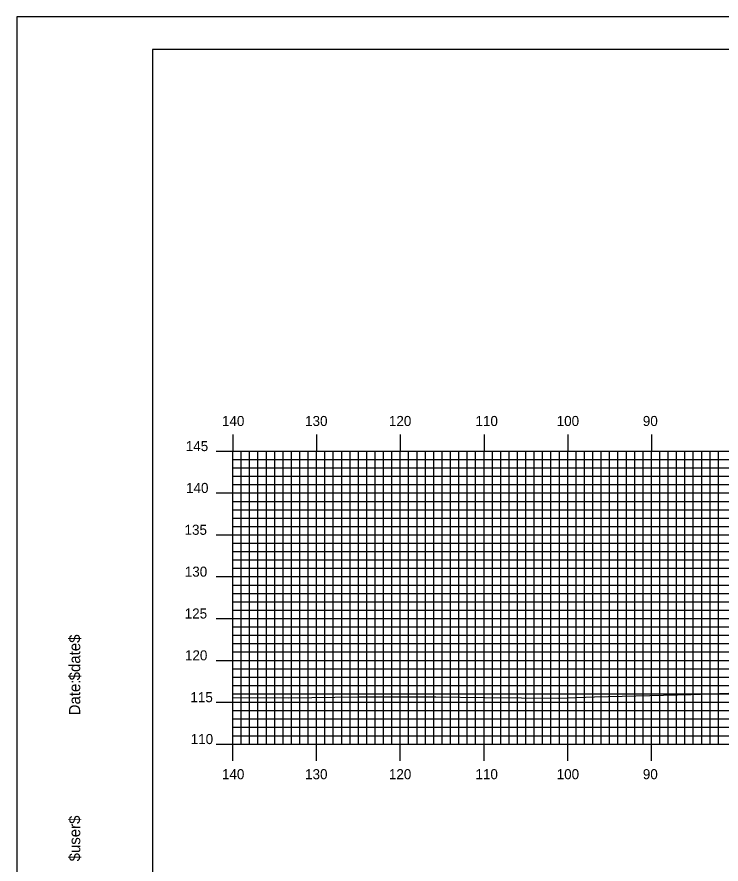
# Model space of a CAD drawing. Extents: x 1789337 to 1789680, y 442591 to 442811.
# Drawn here: x 1789336.9 to 1789421, y 442709.3 to 442810.5 of the extents above; entities that cross this region are included whole.
import ezdxf

# ---------------------------------------------------------------- set-up
doc = ezdxf.new("R2010")
doc.units = 0
for name, color, linetype in [('BORDER', 7, 'Continuous'), ('H_V ANNOTATION', 7, 'Continuous'), ('MAJOR', 7, 'Continuous'), ('MINOR', 7, 'Continuous'), ('PLOT BOUNDARY', 7, 'Continuous'), ('S_Roadway_Centerline', 7, 'Continuous')]:
    doc.layers.add(name, color=color, linetype=linetype)

msp = doc.modelspace()

# ---------------------------------------------------------------- linework, layer by layer
at = {"layer": 'BORDER'}
msp.add_lwpolyline([(1789353.07, 442596.67), (1789673.07, 442596.67), (1789673.07, 442806.67), (1789353.07, 442806.67)], close=True, dxfattribs=at)
at = {"layer": 'MAJOR'}
for p, q in [((1789362.67, 442760.67), (1789362.67, 442758.67)), ((1789372.67, 442760.67), (1789372.67, 442758.67)), ((1789382.67, 442760.67), (1789382.67, 442758.67)), ((1789392.67, 442760.67), (1789392.67, 442758.67)), ((1789402.67, 442760.67), (1789402.67, 442758.67)), ((1789412.67, 442760.67), (1789412.67, 442758.67)), ((1789360.67, 442758.67), (1789362.67, 442758.67)), ((1789362.67, 442758.67), (1789642.67, 442758.67)), ((1789362.67, 442723.67), (1789362.67, 442758.67)), ((1789362.67, 442723.67), (1789362.67, 442758.67)), ((1789362.67, 442758.67), (1789642.67, 442758.67)), ((1789372.67, 442723.67), (1789372.67, 442758.67)), ((1789382.67, 442723.67), (1789382.67, 442758.67)), ((1789392.67, 442723.67), (1789392.67, 442758.67)), ((1789402.67, 442723.67), (1789402.67, 442758.67)), ((1789412.67, 442723.67), (1789412.67, 442758.67)), ((1789360.67, 442753.67), (1789362.67, 442753.67)), ((1789362.67, 442753.67), (1789642.67, 442753.67)), ((1789360.67, 442748.67), (1789362.67, 442748.67)), ((1789362.67, 442748.67), (1789642.67, 442748.67)), ((1789360.67, 442743.67), (1789362.67, 442743.67)), ((1789362.67, 442743.67), (1789642.67, 442743.67)), ((1789360.67, 442738.67), (1789362.67, 442738.67)), ((1789362.67, 442738.67), (1789642.67, 442738.67)), ((1789360.67, 442733.67), (1789362.67, 442733.67)), ((1789362.67, 442733.67), (1789642.67, 442733.67)), ((1789360.67, 442728.67), (1789362.67, 442728.67)), ((1789362.67, 442728.67), (1789642.67, 442728.67)), ((1789360.67, 442723.67), (1789362.67, 442723.67)), ((1789362.67, 442723.67), (1789642.67, 442723.67)), ((1789362.67, 442723.67), (1789642.67, 442723.67)), ((1789362.67, 442721.66), (1789362.67, 442723.67)), ((1789372.67, 442721.66), (1789372.67, 442723.67)), ((1789382.67, 442721.66), (1789382.67, 442723.67)), ((1789392.67, 442721.66), (1789392.67, 442723.67)), ((1789402.67, 442721.66), (1789402.67, 442723.67)), ((1789412.67, 442721.66), (1789412.67, 442723.67))]:
    msp.add_line(p, q, dxfattribs=at)
at = {"layer": 'MINOR'}
for p, q in [((1789363.67, 442723.67), (1789363.67, 442758.67)), ((1789364.67, 442723.67), (1789364.67, 442758.67)), ((1789365.67, 442723.67), (1789365.67, 442758.67)), ((1789366.67, 442723.67), (1789366.67, 442758.67)), ((1789367.67, 442723.67), (1789367.67, 442758.67)), ((1789368.67, 442723.67), (1789368.67, 442758.67)), ((1789369.67, 442723.67), (1789369.67, 442758.67)), ((1789370.67, 442723.67), (1789370.67, 442758.67)), ((1789371.67, 442723.67), (1789371.67, 442758.67)), ((1789373.67, 442723.67), (1789373.67, 442758.67)), ((1789374.67, 442723.67), (1789374.67, 442758.67)), ((1789375.67, 442723.67), (1789375.67, 442758.67)), ((1789376.67, 442723.67), (1789376.67, 442758.67)), ((1789377.67, 442723.67), (1789377.67, 442758.67)), ((1789378.67, 442723.67), (1789378.67, 442758.67)), ((1789379.67, 442723.67), (1789379.67, 442758.67)), ((1789380.67, 442723.67), (1789380.67, 442758.67)), ((1789381.67, 442723.67), (1789381.67, 442758.67)), ((1789383.67, 442723.67), (1789383.67, 442758.67)), ((1789384.67, 442723.67), (1789384.67, 442758.67)), ((1789385.67, 442723.67), (1789385.67, 442758.67)), ((1789386.67, 442723.67), (1789386.67, 442758.67)), ((1789387.67, 442723.67), (1789387.67, 442758.67)), ((1789388.67, 442723.67), (1789388.67, 442758.67)), ((1789389.67, 442723.67), (1789389.67, 442758.67)), ((1789390.67, 442723.67), (1789390.67, 442758.67)), ((1789391.67, 442723.67), (1789391.67, 442758.67)), ((1789393.67, 442723.67), (1789393.67, 442758.67)), ((1789394.67, 442723.67), (1789394.67, 442758.67)), ((1789395.67, 442723.67), (1789395.67, 442758.67)), ((1789396.67, 442723.67), (1789396.67, 442758.67)), ((1789397.67, 442723.67), (1789397.67, 442758.67)), ((1789398.67, 442723.67), (1789398.67, 442758.67)), ((1789399.67, 442723.67), (1789399.67, 442758.67)), ((1789400.67, 442723.67), (1789400.67, 442758.67)), ((1789401.67, 442723.67), (1789401.67, 442758.67)), ((1789403.67, 442723.67), (1789403.67, 442758.67)), ((1789404.67, 442723.67), (1789404.67, 442758.67)), ((1789405.67, 442723.67), (1789405.67, 442758.67)), ((1789406.67, 442723.67), (1789406.67, 442758.67)), ((1789407.67, 442723.67), (1789407.67, 442758.67)), ((1789408.67, 442723.67), (1789408.67, 442758.67)), ((1789409.67, 442723.67), (1789409.67, 442758.67)), ((1789410.67, 442723.67), (1789410.67, 442758.67)), ((1789411.67, 442723.67), (1789411.67, 442758.67)), ((1789413.67, 442723.67), (1789413.67, 442758.67)), ((1789414.67, 442723.67), (1789414.67, 442758.67)), ((1789415.67, 442723.67), (1789415.67, 442758.67)), ((1789416.67, 442723.67), (1789416.67, 442758.67)), ((1789417.67, 442723.67), (1789417.67, 442758.67)), ((1789418.67, 442723.67), (1789418.67, 442758.67)), ((1789419.67, 442723.67), (1789419.67, 442758.67)), ((1789420.67, 442723.67), (1789420.67, 442758.67)), ((1789362.67, 442757.67), (1789642.67, 442757.67)), ((1789362.67, 442757.67), (1789364.67, 442757.67)), ((1789362.67, 442756.67), (1789642.67, 442756.67)), ((1789362.67, 442756.67), (1789364.67, 442756.67)), ((1789362.67, 442755.67), (1789642.67, 442755.67)), ((1789362.67, 442755.67), (1789364.67, 442755.67)), ((1789362.67, 442754.67), (1789642.67, 442754.67)), ((1789362.67, 442754.67), (1789364.67, 442754.67)), ((1789362.67, 442752.67), (1789642.67, 442752.67)), ((1789362.67, 442752.67), (1789364.67, 442752.67)), ((1789362.67, 442751.67), (1789642.67, 442751.67)), ((1789362.67, 442751.67), (1789364.67, 442751.67)), ((1789362.67, 442750.67), (1789642.67, 442750.67)), ((1789362.67, 442750.67), (1789364.67, 442750.67)), ((1789362.67, 442749.67), (1789642.67, 442749.67)), ((1789362.67, 442749.67), (1789364.67, 442749.67)), ((1789362.67, 442747.67), (1789642.67, 442747.67)), ((1789362.67, 442747.67), (1789364.67, 442747.67)), ((1789362.67, 442746.67), (1789642.67, 442746.67)), ((1789362.67, 442746.67), (1789364.67, 442746.67)), ((1789362.67, 442745.67), (1789642.67, 442745.67)), ((1789362.67, 442745.67), (1789364.67, 442745.67)), ((1789362.67, 442744.67), (1789642.67, 442744.67)), ((1789362.67, 442744.67), (1789364.67, 442744.67)), ((1789362.67, 442742.67), (1789642.67, 442742.67)), ((1789362.67, 442742.67), (1789364.67, 442742.67)), ((1789362.67, 442741.67), (1789642.67, 442741.67)), ((1789362.67, 442741.67), (1789364.67, 442741.67)), ((1789362.67, 442740.67), (1789642.67, 442740.67)), ((1789362.67, 442740.67), (1789364.67, 442740.67)), ((1789362.67, 442739.67), (1789642.67, 442739.67)), ((1789362.67, 442739.67), (1789364.67, 442739.67)), ((1789362.67, 442737.67), (1789642.67, 442737.67)), ((1789362.67, 442737.67), (1789364.67, 442737.67)), ((1789362.67, 442736.67), (1789642.67, 442736.67)), ((1789362.67, 442736.67), (1789364.67, 442736.67)), ((1789362.67, 442735.67), (1789642.67, 442735.67)), ((1789362.67, 442735.67), (1789364.67, 442735.67)), ((1789362.67, 442734.67), (1789642.67, 442734.67)), ((1789362.67, 442734.67), (1789364.67, 442734.67)), ((1789362.67, 442732.67), (1789642.67, 442732.67)), ((1789362.67, 442732.67), (1789364.67, 442732.67)), ((1789362.67, 442731.67), (1789642.67, 442731.67)), ((1789362.67, 442731.67), (1789364.67, 442731.67)), ((1789362.67, 442730.67), (1789642.67, 442730.67)), ((1789362.67, 442730.67), (1789364.67, 442730.67)), ((1789362.67, 442729.67), (1789642.67, 442729.67)), ((1789362.67, 442729.67), (1789364.67, 442729.67)), ((1789362.67, 442727.67), (1789642.67, 442727.67)), ((1789362.67, 442727.67), (1789364.67, 442727.67)), ((1789362.67, 442726.67), (1789642.67, 442726.67)), ((1789362.67, 442726.67), (1789364.67, 442726.67)), ((1789362.67, 442725.67), (1789642.67, 442725.67)), ((1789362.67, 442725.67), (1789364.67, 442725.67)), ((1789362.67, 442724.67), (1789642.67, 442724.67)), ((1789362.67, 442724.67), (1789364.67, 442724.67))]:
    msp.add_line(p, q, dxfattribs=at)
at = {"layer": 'PLOT BOUNDARY'}
msp.add_lwpolyline([(1789336.88, 442590.55), (1789676.88, 442590.55), (1789676.88, 442810.55), (1789336.88, 442810.55)], close=True, dxfattribs=at)
at = {"layer": 'S_Roadway_Centerline'}
msp.add_lwpolyline([(1789362.67, 442729.25), (1789369.35, 442729.21), (1789377.59, 442729.33), (1789386.93, 442729.33), (1789392.78, 442729.24), (1789401.53, 442729.15), (1789405.87, 442729.32), (1789417.41, 442729.6), (1789424.15, 442729.81)], dxfattribs=at)

# ---------------------------------------------------------------- texts
at = {"layer": 'BORDER'}
for s, p in [('$date$', (1789344.44, 442731.28)), ('Date:', (1789344.44, 442727.1)), ('$user$', (1789344.44, 442709.65))]:
    msp.add_text(s, height=1.339, rotation=90, dxfattribs=at).set_placement(p)
at = {"layer": 'H_V ANNOTATION'}
for s, p in [('140', (1789361.37, 442761.67)), ('130', (1789371.3, 442761.67)), ('120', (1789381.31, 442761.67)), ('110', (1789391.65, 442761.67)), ('100', (1789401.35, 442761.67)), ('90', (1789411.64, 442761.67)), ('145', (1789357.05, 442758.67)), ('140', (1789357.08, 442753.67)), ('135', (1789356.9, 442748.67)), ('130', (1789356.93, 442743.67)), ('125', (1789356.92, 442738.67)), ('120', (1789356.95, 442733.67)), ('115', (1789357.6, 442728.67)), ('110', (1789357.64, 442723.67)), ('140', (1789361.37, 442719.47)), ('130', (1789371.3, 442719.47)), ('120', (1789381.31, 442719.47)), ('110', (1789391.65, 442719.47)), ('100', (1789401.35, 442719.47)), ('90', (1789411.64, 442719.47))]:
    msp.add_text(s, height=1.2, dxfattribs=at).set_placement(p)
at = {"layer": 'MAJOR'}
msp.add_text('-', height=0.012, dxfattribs=at).set_placement((1789362.66, 442723.67))

doc.saveas('drawing.dxf')
